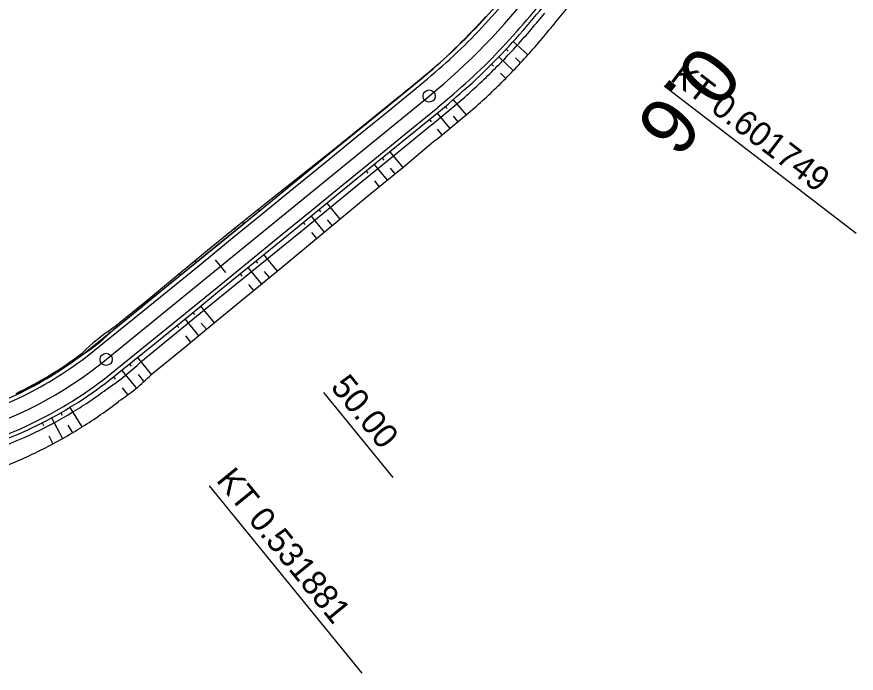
# Model space of a CAD drawing. Extents: x -481645 to -478728, y -1113199 to -1110710.
# Drawn here: x -479536.3 to -479433.2, y -1111452.2 to -1111371.6 of the extents above; entities that cross this region are included whole.
import ezdxf

# ---------------------------------------------------------------- set-up
doc = ezdxf.new("R2010")
doc.units = 0
for name, color, linetype in [('CP14_HATCH_SLOPE_L', 7, 'Continuous'), ('CP1_HECTOMETRY', 7, 'Continuous'), ('O6_HATCH_SLOPE_L', 7, 'Continuous'), ('O6_HATCH_SLOPE_R', 7, 'Continuous'), ('O6_HECTOMETRY', 7, 'Continuous'), ('O6_HLBODY', 7, 'Continuous'), ('O6_HRANA_TELESO', 7, 'Continuous'), ('O6_OSA', 7, 'Continuous'), ('O6_VOZOVKA', 7, 'Continuous'), ('O6_ZPEVKRAJ', 7, 'Continuous')]:
    doc.layers.add(name, color=color, linetype=linetype)

msp = doc.modelspace()

# ---------------------------------------------------------------- linework, layer by layer
at = {"layer": 'CP14_HATCH_SLOPE_L'}
for p, q in [((-479475.31, -1111374.61), (-479473.52, -1111376.24)), ((-479476.18, -1111375.55), (-479475.94, -1111375.78)), ((-479477.07, -1111376.48), (-479475.31, -1111378.18)), ((-479475.05, -1111376.61), (-479474.41, -1111377.22)), ((-479477.97, -1111377.4), (-479477.73, -1111377.63)), ((-479476.87, -1111378.5), (-479476.24, -1111379.13)), ((-479482.68, -1111381.77), (-479481.1, -1111383.62)), ((-479483.67, -1111382.59), (-479483.45, -1111382.85)), ((-479484.65, -1111383.4), (-479483.11, -1111385.28)), ((-479482.68, -1111383.79), (-479482.11, -1111384.47)), ((-479485.62, -1111384.19), (-479485.41, -1111384.45)), ((-479484.64, -1111385.39), (-479484.08, -1111386.07)), ((-479490.46, -1111388.14), (-479488.89, -1111390.07)), ((-479491.43, -1111388.93), (-479491.22, -1111389.18)), ((-479492.4, -1111389.72), (-479490.82, -1111391.65)), ((-479490.43, -1111390.15), (-479489.85, -1111390.86)), ((-479493.37, -1111390.51), (-479493.16, -1111390.76)), ((-479492.37, -1111391.73), (-479491.79, -1111392.44)), ((-479499.18, -1111395.24), (-479498.97, -1111395.5)), ((-479498.21, -1111394.45), (-479496.61, -1111396.42)), ((-479500.15, -1111396.03), (-479498.54, -1111398.01)), ((-479498.17, -1111396.49), (-479497.57, -1111397.22)), ((-479501.12, -1111396.82), (-479500.91, -1111397.08)), ((-479500.1, -1111398.07), (-479499.5, -1111398.81)), ((-479506.93, -1111401.56), (-479506.72, -1111401.82)), ((-479505.97, -1111400.77), (-479504.32, -1111402.79)), ((-479507.9, -1111402.35), (-479506.25, -1111404.38)), ((-479508.87, -1111403.14), (-479508.66, -1111403.4)), ((-479505.9, -1111402.83), (-479505.28, -1111403.58)), ((-479507.83, -1111404.42), (-479507.21, -1111405.18)), ((-479513.72, -1111407.09), (-479512.04, -1111409.15)), ((-479515.66, -1111408.67), (-479513.97, -1111410.74)), ((-479514.69, -1111407.88), (-479514.48, -1111408.14)), ((-479516.62, -1111409.46), (-479516.41, -1111409.72)), ((-479513.64, -1111409.17), (-479513, -1111409.94)), ((-479515.57, -1111410.75), (-479514.94, -1111411.53)), ((-479521.47, -1111413.41), (-479519.77, -1111415.5)), ((-479523.41, -1111414.99), (-479521.69, -1111417.09)), ((-479522.44, -1111414.2), (-479522.23, -1111414.45)), ((-479524.4, -1111415.79), (-479524.19, -1111416.05)), ((-479521.37, -1111415.5), (-479520.73, -1111416.29)), ((-479523.34, -1111417.12), (-479522.7, -1111417.93)), ((-479530.88, -1111420.19), (-479530.71, -1111420.48)), ((-479529.76, -1111419.52), (-479528.29, -1111421.93)), ((-479532.02, -1111420.82), (-479530.66, -1111423.34)), ((-479533.18, -1111421.43), (-479533.03, -1111421.73)), ((-479530.01, -1111421.71), (-479529.47, -1111422.65)), ((-479532.37, -1111423.02), (-479531.86, -1111424.01))]:
    msp.add_line(p, q, dxfattribs=at)
at = {"layer": 'CP1_HECTOMETRY'}
msp.add_line((-479525.99, -1111414.19), (-479485.64, -1111381.3), dxfattribs=at)
for centre, radius, start, end in [((-479536.18, -1111319.29), 80, 309.1801, 322.5669), ((-479556.9, -1111374.87), 50, 285.9337, 309.1802)]:
    msp.add_arc(centre, radius, start, end, dxfattribs=at)
at = {"layer": 'O6_HATCH_SLOPE_R'}
for p, q in [((-479479.15, -1111372.09), (-479479.17, -1111372.07)), ((-479479.13, -1111372.11), (-479479.13, -1111372.11)), ((-479483.43, -1111376.4), (-479483.45, -1111376.38)), ((-479484.34, -1111377.2), (-479484.35, -1111377.19)), ((-479484.33, -1111377.22), (-479484.33, -1111377.22)), ((-479486.18, -1111378.79), (-479486.18, -1111378.78)), ((-479486.16, -1111378.81), (-479486.16, -1111378.81)), ((-479485.24, -1111378.02), (-479485.26, -1111378)), ((-479490.97, -1111382.75), (-479491, -1111382.71)), ((-479491.96, -1111383.51), (-479491.97, -1111383.5)), ((-479491.94, -1111383.54), (-479491.95, -1111383.53)), ((-479493.9, -1111385.09), (-479493.91, -1111385.08)), ((-479493.88, -1111385.12), (-479493.88, -1111385.11)), ((-479492.91, -1111384.33), (-479492.94, -1111384.29)), ((-479498.73, -1111389.06), (-479498.79, -1111388.98)), ((-479499.74, -1111389.8), (-479499.77, -1111389.76)), ((-479499.69, -1111389.85), (-479499.7, -1111389.85)), ((-479501.69, -1111391.37), (-479501.73, -1111391.31)), ((-479500.66, -1111390.64), (-479500.75, -1111390.53)), ((-479501.63, -1111391.43), (-479501.64, -1111391.43)), ((-479506.48, -1111395.38), (-479506.63, -1111395.19)), ((-479507.53, -1111396.07), (-479507.6, -1111395.98)), ((-479507.45, -1111396.17), (-479507.45, -1111396.17)), ((-479508.41, -1111396.96), (-479508.58, -1111396.76)), ((-479509.47, -1111397.64), (-479509.55, -1111397.54)), ((-479509.38, -1111397.75), (-479509.39, -1111397.75)), ((-479514.23, -1111401.7), (-479514.39, -1111401.5)), ((-479515.28, -1111402.39), (-479515.36, -1111402.29)), ((-479515.2, -1111402.49), (-479515.2, -1111402.49)), ((-479516.17, -1111403.28), (-479516.33, -1111403.08)), ((-479517.22, -1111403.97), (-479517.29, -1111403.88)), ((-479517.14, -1111404.07), (-479517.14, -1111404.06)), ((-479523.02, -1111408.72), (-479523.08, -1111408.65)), ((-479522.95, -1111408.81), (-479522.95, -1111408.8)), ((-479521.98, -1111408.02), (-479522.11, -1111407.85)), ((-479523.92, -1111409.6), (-479524.05, -1111409.44)), ((-479524.95, -1111410.3), (-479525.01, -1111410.23)), ((-479524.89, -1111410.39), (-479524.89, -1111410.38)), ((-479532.09, -1111415.68), (-479532.18, -1111415.53)), ((-479534.16, -1111416.87), (-479534.24, -1111416.72)), ((-479533.16, -1111416.21), (-479533.2, -1111416.14)), ((-479533.12, -1111416.28), (-479533.12, -1111416.28)), ((-479535.26, -1111417.35), (-479535.29, -1111417.28)), ((-479535.22, -1111417.42), (-479535.22, -1111417.42))]:
    msp.add_line(p, q, dxfattribs=at)
at = {"layer": 'O6_HECTOMETRY'}
for p, q in [((-479456.77, -1111380.07), (-479433.19, -1111398.12)), ((-479512.67, -1111429.14), (-479493.91, -1111452.16))]:
    msp.add_line(p, q, dxfattribs=at)
for centre in [(-479485.64, -1111381.3), (-479525.31, -1111413.63)]:
    msp.add_circle(centre, 0.75, dxfattribs=at)
at = {"layer": 'O6_HLBODY'}
for p, q in [((-479510.63, -1111402.96), (-479511.89, -1111401.41)), ((-479498.63, -1111417.69), (-479490.1, -1111428.15))]:
    msp.add_line(p, q, dxfattribs=at)
at = {"layer": 'O6_HRANA_TELESO'}
for p, q in [((-479493.31, -1111384.64), (-479489.43, -1111381.48)), ((-479497.19, -1111387.8), (-479493.31, -1111384.64)), ((-479490.04, -1111388.65), (-479486.17, -1111385.49)), ((-479501.06, -1111390.96), (-479497.19, -1111387.8)), ((-479493.92, -1111391.81), (-479490.04, -1111388.65)), ((-479504.94, -1111394.12), (-479501.06, -1111390.96)), ((-479497.79, -1111394.97), (-479493.92, -1111391.81)), ((-479508.81, -1111397.27), (-479504.94, -1111394.12)), ((-479501.67, -1111398.13), (-479497.79, -1111394.97)), ((-479512.69, -1111400.43), (-479508.81, -1111397.27)), ((-479505.54, -1111401.29), (-479501.67, -1111398.13)), ((-479516.57, -1111403.59), (-479512.69, -1111400.43)), ((-479509.42, -1111404.45), (-479505.54, -1111401.29)), ((-479520.44, -1111406.75), (-479516.57, -1111403.59)), ((-479513.3, -1111407.6), (-479509.42, -1111404.45)), ((-479524.32, -1111409.91), (-479520.44, -1111406.75)), ((-479517.17, -1111410.76), (-479513.3, -1111407.6)), ((-479521.05, -1111413.92), (-479517.17, -1111410.76))]:
    msp.add_line(p, q, dxfattribs=at)
for centre, radius, start, end in [((-479536.18, -1111319.29), 77.74, 314.1525, 317.7335), ((-479536.18, -1111319.29), 82.92, 317.7335, 321.3145), ((-479536.18, -1111319.29), 77.74, 310.5715, 314.1525), ((-479536.18, -1111319.29), 82.92, 314.1525, 317.7335), ((-479635.69, -1111199.82), 233.22, 308.8383, 310.0532), ((-479536.18, -1111319.29), 82.92, 310.5715, 314.1525), ((-479642.28, -1111191.83), 248.75, 308.8724, 310.0404), ((-479541.11, -1111392.94), 23.87, 302.8775, 314.6953), ((-479556.9, -1111374.87), 47.74, 301.2953, 307.0249), ((-479539.53, -1111394.99), 26.46, 303.2195, 314.3012), ((-479556.9, -1111374.87), 47.74, 295.5657, 301.2953), ((-479556.9, -1111374.87), 52.92, 301.2953, 307.0249), ((-479556.9, -1111374.87), 52.92, 295.5657, 301.2953), ((-479556.9, -1111374.87), 52.92, 289.8361, 295.5657)]:
    msp.add_arc(centre, radius, start, end, dxfattribs=at)
at = {"layer": 'O6_OSA'}
for p, q in [((-479493.34, -1111384.61), (-479489.46, -1111381.46)), ((-479497.23, -1111387.75), (-479493.34, -1111384.61)), ((-479488.89, -1111390.07), (-479485.05, -1111386.86)), ((-479501.15, -1111390.85), (-479497.23, -1111387.75)), ((-479492.76, -1111393.23), (-479488.89, -1111390.07)), ((-479505.07, -1111393.96), (-479501.15, -1111390.85)), ((-479496.61, -1111396.42), (-479492.76, -1111393.23)), ((-479508.99, -1111397.06), (-479505.07, -1111393.96)), ((-479500.47, -1111399.6), (-479496.61, -1111396.42)), ((-479512.85, -1111400.24), (-479508.99, -1111397.06)), ((-479516.72, -1111403.41), (-479512.85, -1111400.24)), ((-479504.32, -1111402.79), (-479500.47, -1111399.6)), ((-479520.57, -1111406.59), (-479516.72, -1111403.41)), ((-479508.18, -1111405.97), (-479504.32, -1111402.79)), ((-479524.44, -1111409.76), (-479520.57, -1111406.59)), ((-479512.04, -1111409.15), (-479508.18, -1111405.97)), ((-479515.9, -1111412.32), (-479512.04, -1111409.15)), ((-479519.77, -1111415.5), (-479515.9, -1111412.32))]:
    msp.add_line(p, q, dxfattribs=at)
for centre, radius, start, end in [((-479502, -1111344.39), 42.33, 318.9236, 325.8334), ((-479536.51, -1111319.63), 77.7, 314.5054, 318.0864), ((-479536.39, -1111319.54), 84.67, 317.9557, 321.5367), ((-479536.12, -1111319.24), 77.72, 310.5149, 314.0959), ((-479536.52, -1111319.65), 84.69, 314.4898, 318.0708), ((-479635.44, -1111199.68), 233.14, 308.769, 309.9841), ((-479535.95, -1111319.08), 84.7, 310.3672, 313.9482), ((-479644.14, -1111188.76), 254.07, 308.7674, 309.9206), ((-479511.47, -1111429.7), 23.78, 123.0473, 134.8927), ((-479557.03, -1111374.97), 47.57, 301.4916, 307.2212), ((-479557.01, -1111374.94), 47.59, 295.727, 301.4566), ((-479539.1, -1111395.94), 27.5, 303.8489, 314.6741), ((-479557.49, -1111375.29), 55.03, 302.0493, 307.7794), ((-479557.79, -1111375.37), 55.12, 296.6235, 302.354), ((-479557.96, -1111375.33), 55.23, 291.0412, 296.7721)]:
    msp.add_arc(centre, radius, start, end, dxfattribs=at)
at = {"layer": 'O6_VOZOVKA'}
for p, q in [((-479490.66, -1111383.14), (-479486.78, -1111379.98)), ((-479488.45, -1111385.85), (-479484.57, -1111382.69)), ((-479494.53, -1111386.29), (-479490.66, -1111383.14)), ((-479492.32, -1111389.01), (-479488.45, -1111385.85)), ((-479498.41, -1111389.45), (-479494.53, -1111386.29)), ((-479496.2, -1111392.17), (-479492.32, -1111389.01)), ((-479502.29, -1111392.61), (-479498.41, -1111389.45)), ((-479500.07, -1111395.32), (-479496.2, -1111392.17)), ((-479506.16, -1111395.77), (-479502.29, -1111392.61)), ((-479503.95, -1111398.48), (-479500.07, -1111395.32)), ((-479510.04, -1111398.93), (-479506.16, -1111395.77)), ((-479507.83, -1111401.64), (-479503.95, -1111398.48)), ((-479513.91, -1111402.09), (-479510.04, -1111398.93)), ((-479511.7, -1111404.8), (-479507.83, -1111401.64)), ((-479517.79, -1111405.25), (-479513.91, -1111402.09)), ((-479521.66, -1111408.41), (-479517.79, -1111405.25)), ((-479515.58, -1111407.96), (-479511.7, -1111404.8)), ((-479527.84, -1111413.4), (-479521.66, -1111408.41)), ((-479519.45, -1111411.12), (-479515.58, -1111407.96)), ((-479525.73, -1111416.19), (-479519.45, -1111411.12))]:
    msp.add_line(p, q, dxfattribs=at)
for centre, radius, start, end in [((-479504.03, -1111344.61), 40.88, 317.9957, 325.1228), ((-479536.18, -1111319.29), 78.25, 316.3068, 319.8878), ((-479536.18, -1111319.29), 81.75, 316.3068, 319.8878), ((-479536.18, -1111319.29), 78.25, 312.7258, 316.3068), ((-479536.18, -1111319.29), 81.75, 312.7259, 316.3068), ((-479638.73, -1111201.04), 234.75, 310.3383, 311.532), ((-479643.32, -1111195.75), 245.25, 310.3393, 311.5325), ((-479556.9, -1111374.87), 48.25, 301.2953, 307.0249), ((-479556.9, -1111374.87), 48.25, 295.5657, 301.2953), ((-479556.9, -1111374.87), 51.75, 301.2953, 307.0249), ((-479556.9, -1111374.87), 48.25, 289.8361, 295.5657), ((-479556.9, -1111374.87), 51.75, 295.5657, 301.2953), ((-479556.9, -1111374.87), 51.75, 289.8361, 295.5657)]:
    msp.add_arc(centre, radius, start, end, dxfattribs=at)
at = {"layer": 'O6_ZPEVKRAJ'}
for p, q in [((-479490.97, -1111382.75), (-479487.1, -1111379.59)), ((-479494.85, -1111385.91), (-479490.97, -1111382.75)), ((-479488.13, -1111386.24), (-479484.25, -1111383.08)), ((-479498.73, -1111389.06), (-479494.85, -1111385.91)), ((-479492.01, -1111389.39), (-479488.13, -1111386.24)), ((-479502.6, -1111392.22), (-479498.73, -1111389.06)), ((-479495.88, -1111392.55), (-479492.01, -1111389.39)), ((-479506.48, -1111395.38), (-479502.6, -1111392.22)), ((-479499.76, -1111395.71), (-479495.88, -1111392.55)), ((-479510.35, -1111398.54), (-479506.48, -1111395.38)), ((-479503.63, -1111398.87), (-479499.76, -1111395.71)), ((-479514.23, -1111401.7), (-479510.35, -1111398.54)), ((-479507.51, -1111402.03), (-479503.63, -1111398.87)), ((-479518.1, -1111404.86), (-479514.23, -1111401.7)), ((-479511.39, -1111405.19), (-479507.51, -1111402.03)), ((-479521.98, -1111408.02), (-479518.1, -1111404.86)), ((-479515.26, -1111408.35), (-479511.39, -1111405.19)), ((-479528.14, -1111413), (-479521.98, -1111408.02)), ((-479519.14, -1111411.51), (-479515.26, -1111408.35)), ((-479525.43, -1111416.59), (-479519.14, -1111411.51))]:
    msp.add_line(p, q, dxfattribs=at)
for centre, radius, start, end in [((-479503.84, -1111344.76), 41.12, 317.9996, 325.1159), ((-479536.18, -1111319.29), 77.75, 316.3068, 319.8878), ((-479536.18, -1111319.29), 82.25, 316.3068, 319.8878), ((-479536.18, -1111319.29), 77.75, 312.7258, 316.3068), ((-479638.08, -1111201.8), 233.25, 310.3381, 311.5319), ((-479536.18, -1111319.29), 82.25, 312.7259, 316.3068), ((-479643.98, -1111195), 246.75, 310.3394, 311.5326), ((-479556.9, -1111374.87), 47.75, 301.2953, 307.0249), ((-479556.9, -1111374.87), 47.75, 295.5657, 301.2953), ((-479556.9, -1111374.87), 52.25, 301.2953, 307.0249), ((-479556.9, -1111374.87), 47.75, 289.8361, 295.5657), ((-479556.9, -1111374.87), 52.25, 295.5657, 301.2953), ((-479556.9, -1111374.87), 52.25, 289.8361, 295.5657)]:
    msp.add_arc(centre, radius, start, end, dxfattribs=at)

# ---------------------------------------------------------------- texts
at = {"layer": 'O6_HATCH_SLOPE_L'}
msp.add_text('0.6', height=6.999, rotation=231.2688, dxfattribs=at).set_placement((-479452.36, -1111374.61))
at = {"layer": 'O6_HECTOMETRY'}
for s, height, rotation, p in [('KT 0.601749', 2.999, 322.5669, (-479456.17, -1111379.28)), ('KT 0.531881', 3, 309.1802, (-479511.9, -1111428.5))]:
    msp.add_text(s, height=height, rotation=rotation, dxfattribs=at).set_placement(p)
at = {"layer": 'O6_HLBODY'}
msp.add_text('50.00', height=3, rotation=309.1802, dxfattribs=at).set_placement((-479497.85, -1111417.06))

doc.saveas('drawing.dxf')
